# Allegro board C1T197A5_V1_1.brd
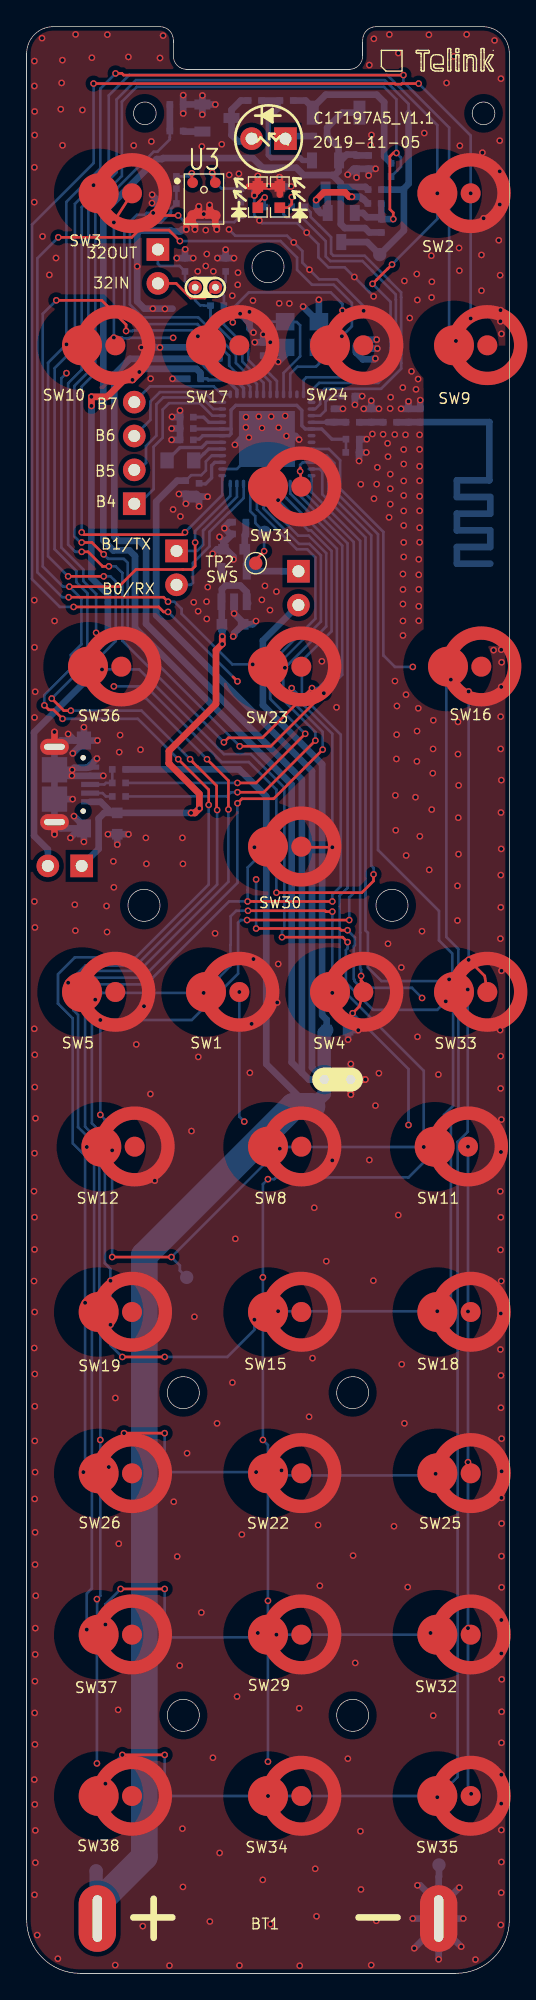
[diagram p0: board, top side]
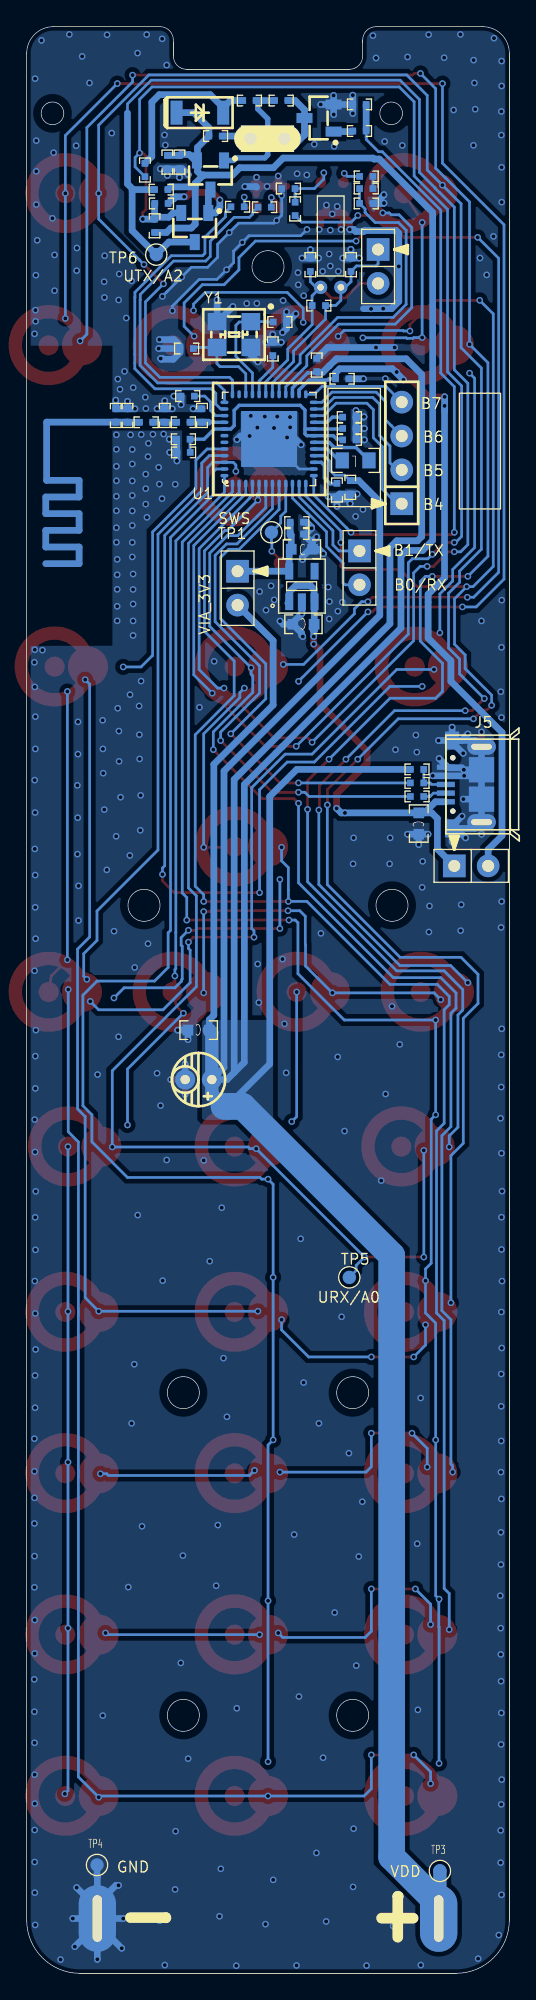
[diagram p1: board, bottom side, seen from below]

Outline 36.2 x 146 mm; copper layers: TOP, BOTTOM. Coordinates in mm from the lower left corner of the outline.
Outline path: circle c8.8,80.1 r1.2 ; circle c8.86,139.5 r0.85 ; circle c11.75,43.55 r1.2 ; circle c11.75,19.35 r1.2 ; circle c18.1,128 r1.2 ; circle c24.45,43.55 r1.2 ; circle c24.45,19.35 r1.2 ; circle c27.4,80.1 r1.2 ; circle c34.26,139.5 r0.85 ; 0,144 0,4 ; 0,144 arc(0.59,145.41) 2,146 10,146 arc(10.71,145.71) 11,145 ; 0,144 0,4 ; 0,4 arc(1.17,1.17) 4,0 ; 4,0 32.2,0 ; 4,0 32.2,0 ; 32.2,0 arc(35.03,1.17) 36.2,4 36.2,144 arc(35.61,145.41) 34.2,146 26.2,146 arc(25.49,145.71) 25.2,145 25.2,144.8 ; 11,145 11,144.8 ; 11,145 11,144.8 ; 11,144.8 11,143.8 arc(11.29,143.09) 12,142.8 ; 12,142.8 24.2,142.8 ; 12,142.8 24.2,142.8 ; 24.2,142.8 arc(24.91,143.09) 25.2,143.8 ; 25.2,144.8 25.2,143.8 ; 25.2,144.8 25.2,143.8

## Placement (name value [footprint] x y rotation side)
BT1  3V_2xAAA  [BAT_2DIP]  18.1 4.11 0 top
C1  NC  [0402]  23.05 116.84 270 bottom
C2  1.2pF  [0402]  25.84 116.84 270 bottom
C3  2.7pF  [0402]  28.64 116.84 270 bottom
C4  220pF  [0402]  24.45 116.33 0 bottom
C5  0.1uF  [0402]  24.45 115.06 180 bottom
C6  2.2uF  [0402]  24.43 114.07 180 bottom
C7  1uF  [0402]  24.12 118.29 0 bottom
C8  1.5pF  [0402]  29.52 116.84 90 bottom
C9  1uF  [0402]  17.74 121.83 270 bottom
C10  1uF  [0402]  14.45 120.62 90 bottom
C11  1uF  [0402]  12.54 119.59 180 bottom
C12  1uF  [0402]  12.93 111.25 90 bottom
C13  NC  [0402]  24.2 121.86 180 bottom
C14  NC  [0402]  17.21 123.85 0 bottom
C15  1uF  [0402]  11.93 111.45 90 bottom
C16  1uF  [0402]  12 115.01 0 bottom
C17  0.1uF  [0402]  12 115.86 0 bottom
C18  1uF  [0402]  12 116.71 0 bottom
C19  NC  [0402]  11.87 128.14 270 bottom
C20  NC  [0402]  14.92 128.14 270 bottom
C21  NC/10uF  [0603C]  15.56 106.81 180 bottom
C22  NC/0.1uF  [0402]  15.94 107.95 180 bottom
C23  NC/10uF  [0603C]  15.44 101.18 0 bottom
C24  10uF  [0603C]  23.3 70.74 0 bottom
C25  NC/10uF  [0603C]  6.79 86.23 270 bottom
C26  10nF  [0402]  10.73 134.77 0 bottom
C27  10pF  [0402]  10.73 132.74 180 bottom
C28  4.7uF  [0402]  16.57 133.86 0 bottom
C31  4.7uF  [0402]  24.74 135.84 270 bottom
C32  0.1uF  [0402]  25.65 135.84 270 bottom
C33  NC/1nF  [0402]  15.94 108.84 180 bottom
CD1  NC  [CD2P0_4P0B]  23.31 67.03 0 bottom
D1  Red_LED  [0603-LED]  17.34 133.22 90 top
D2  Red_LED  [0603-LED]  18.99 133.22 90 top
D3  LED  [LED_TH_2P54MM_2PIN]  18.14 137.6 0 top
D4  1N4148  [SOD80]  23.21 139.55 180 bottom
J1  NC/HEADER 4  [HDR254F-1X4X850]  8.07 117.84 270 bottom
J2  NC/HEADER 2  [HDR254F-1X2X850]  11.24 104.14 90 bottom
J3  HEADER 2  [HDR254F-1X2X850]  9.84 126.75 90 bottom
J4  NC/2PIN  [HDR254F-1X2X850]  20.38 102.62 90 bottom
J5  NC/USB_MiniABF  [MICROUSB_DIP]  4.76 87.87 90 bottom
J42  RF_SOC_5V  [HDR254F-1X2X850]  1.59 83.06 0 bottom
L1  2.7nH  [0402]  27.24 116.33 0 bottom
L3  4.7uH  [0805L]  11.53 113.47 0 bottom
Q1  A1015  [SOT-23]  22.41 134.87 0 bottom
Q2  C1815  [SOT-23]  14.27 139.15 90 bottom
Q3  C1815  [SOT-23]  23.59 130.94 0 bottom
R1  1K  [0402]  18.35 132.46 180 bottom
R2  1K  [0402]  20.38 132.49 180 bottom
R3  NC  [0402]  14.29 125.08 0 bottom
R4  NC/33  [0402]  6.92 88.27 180 bottom
R5  NC/33  [0402]  6.92 89.28 180 bottom
R6  NC/1.5K  [0402]  6.92 90.3 0 bottom
R7  0R  [0402]  16.06 132.33 90 bottom
R8  000R  [0402]  10.73 133.86 180 bottom
R10  1  [0402]  22.03 137.79 0 bottom
R11  NC  [0402]  11.24 140.17 180 bottom
R12  10K  [0402]  26.11 133.78 180 bottom
R13  100  [0402]  11.24 138.18 0 bottom
R14  10K  [0402]  17.11 140.46 0 bottom
R15  22K  [0402]  19.49 140.46 0 bottom
R16  10K  [0402]  26.09 132.74 180 bottom
R17  47K  [0402]  27.33 135.25 270 bottom
R18  NC  [0402]  26.61 131.06 90 bottom
SW1  SW2PIN  [SW_OUT6_IN3]  13.45 73.6 180 top
SW2  SW2PIN  [SW_OUT6_IN3]  30.8 133.5 180 top
SW3  SW2PIN  [SW_OUT6_IN3]  5.4 133.5 180 top
SW4  SW2PIN  [SW_OUT6_IN3]  22.75 73.6 180 top
SW5  SW2PIN  [SW_OUT6_IN3]  4.15 73.6 180 top
SW8  SW2PIN  [SW_OUT6_IN3]  18.1 62 180 top
SW9  SW2PIN  [SW_OUT6_IN3]  32.05 122.1 180 top
SW10  SW2PIN  [SW_OUT6_IN3]  4.15 122.1 180 top
SW11  SW2PIN  [SW_OUT6_IN3]  30.6 62 180 top
SW12  SW2PIN  [SW_OUT6_IN3]  5.6 62 180 top
SW15  SW2PIN  [SW_OUT6_IN3]  18.1 49.6 180 top
SW16  SW2PIN  [SW_OUT6_IN3]  31.6 98 180 top
SW17  SW2PIN  [SW_OUT6_IN3]  13.45 122.1 180 top
SW18  SW2PIN  [SW_OUT6_IN3]  30.8 49.6 180 top
SW19  SW2PIN  [SW_OUT6_IN3]  5.4 49.6 180 top
SW22  SW2PIN  [SW_OUT6_IN3]  18.1 37.5 180 top
SW23  SW2PIN  [SW_OUT6_IN3]  18.1 98 180 top
SW24  SW2PIN  [SW_OUT6_IN3]  22.75 122.1 180 top
SW25  SW2PIN  [SW_OUT6_IN3]  30.8 37.5 180 top
SW26  SW2PIN  [SW_OUT6_IN3]  5.4 37.5 180 top
SW29  SW2PIN  [SW_OUT6_IN3]  18.1 25.4 180 top
SW30  SW2PIN  [SW_OUT6_IN3]  18.1 84.5 180 top
SW31  SW2PIN  [SW_OUT6_IN3]  18.1 111.5 180 top
SW32  SW2PIN  [SW_OUT6_IN3]  30.8 25.4 180 top
SW33  SW2PIN  [SW_OUT6_IN3]  32.05 73.6 180 top
SW34  SW2PIN  [SW_OUT6_IN3]  18.1 13.3 180 top
SW35  SW2PIN  [SW_OUT6_IN3]  30.8 13.3 180 top
SW36  SW2PIN  [SW_OUT6_IN3]  4.6 98 180 top
SW37  SW2PIN  [SW_OUT6_IN3]  5.4 25.4 180 top
SW38  SW2PIN  [SW_OUT6_IN3]  5.4 13.3 180 top
TP1  SWS  [TP100]  17.84 108.08 180 bottom
TP2  SWS  [TP100]  17.18 105.76 0 top
TP3  VDD  [TP100]  5.21 7.68 180 bottom
TP4  GND  [TP100]  30.92 8.13 180 bottom
TP5  URX  [TP100]  12 52.2 180 bottom
TP6  UTX  [TP100]  26.48 128.91 180 bottom
U1  TLSR8278F1KET48  [QFN_7X7_48PIN_0P5_4P20X4P20]  18.02 115.08 90 bottom
U2  CE1132-33M  [SOT-23-5]  15.56 104.01 180 bottom
U3  MWW7037AT2  [GA_BFA423_A83]  13.3 133.07 0 top
Y1  24MHz-12pF-+/-20ppm  [OSCCC250X320X110]  20.65 122.91 270 bottom
Y2  32.768KHz - 9pf - +/-20ppm  [OSC_2X6]  13.4 130.45 270 bottom

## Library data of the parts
BT1 = BATTERY_2xAAA_3V
C1-C4 C8 C19 C20 = C1608_NC
C5-C7 C9-C11 C22 C32 C33 = C1005X5R1C104K
C12 C15-C18 = C1005X5R1C105K
C13 C14 = C1005_NC
C21 C23 C25 = C1608X5R1A106K
C24 = C1608X5R0J106M
C26-C28 = C1608X5R0J475M
C31 = C1608X5R1A226M
CD1 = CD_220uF_16V
D1 D2 = 0603D_Red
D3 = Led_Th_3mm_1: User Part Number: partnum; Tolerance: RichardLC
D4 = Diode_1N4148
J1 = HEADER 4: User Part Number: pn; Tolerance: RichardLC
J2 J3 = HEADER 2: User Part Number: pn; Tolerance: RichardLC
J4 = B2S_2: User Part Number: pn; Tolerance: RichardLC
J5 = USB_MiniABF_2
J42 = B2S_3: User Part Number: pn; Tolerance: RichardLC
L1 = MLK1608_000R
L3 = IND_0
Q1 = PNP_A1015
Q2 Q3 = NPN_C1815
R1 R2 R6-R8 = RS0402K472JT
R3 = RS0603K102JT
R4 R5 = RS0402K330JT
R10 = RS0805K1R0JT
R11 R18 = RS0402_NC
R12 R14 R16 = RS0402K103JT
R13 = RS0402K101JT
R15 = RS0402K223JT
R17 = RS0402K473JT
SW1-SW5 SW8-SW12 SW15-SW19 SW22-SW26 SW29-SW38 = SW2PIN_0
TP1-TP6 = TestPad100
U1 = TLSR8278F1KET48_2
U2 = XC6219_6.3V_SOT-23-5
U3 = MULPS4CX-RM5_0
Y1 = CRYSTAL4/SM_0: Tolerance: RichardLC
Y2 = OSC_2x6_2pin_16Mhz

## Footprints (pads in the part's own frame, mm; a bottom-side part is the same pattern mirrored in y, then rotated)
0402
  rect 0.5x0.5 smd: 1(-0.5,0) 2(0.5,0)
0603-LED
  rect 0.8x0.8 smd: A(-0.8,0) C(0.8,0)
0603C
  rect 0.8x0.8 smd: 1(-0.8,0) 2(0.8,0)
0805L
  rect 1x1.2 smd: 1(-1,0) 2(1,0)
BAT_2DIP
  oval 2.8x5 hole 0.7x3.5: 1(-12.8,0) 2(12.8,0)
CD2P0_4P0B
  round 1.5 hole 0.7: 1(-1,0) 2(1,0)
GA_BFA423_A83
  round 0.8 smd: 1(-0.85,1.23) 2(-0.85,-1.23) 3(0.85,-1.23) 4(0.85,1.23)
HDR254F-1X2X850
  rect 1.7x1.7 hole 0.9: 1(2.54,0)
  round 1.7 hole 0.9: 2(0,0)
HDR254F-1X4X850
  rect 1.7x1.7 hole 0.9: 1(7.62,0)
  round 1.7 hole 0.9: 2(5.08,0) 3(2.54,0) 4(0,0)
LED_TH_2P54MM_2PIN
  rect 1.7x1.7 hole 0.9: A(1.27,0)
  round 1.7 hole 0.9: C(-1.27,0)
MICROUSB_DIP
  round 0.4 hole 0.6 unplated: (-0.7,-0.525) (3.3,-0.525)
  rect 0.4x1.35 smd: 1(0,0) 2(0.65,0) 3(1.3,0) 4(1.95,0) 5(2.6,0)
  oval 1.2x2.15 hole 0.45x1.55: 6(-1.525,-2.675) 7(4.125,-2.675)
  rect 1.9x1.9 smd: 8(0.2,-2.675) 9(2.4,-2.675)
  rect 1.35x1.07 smd: 10(-1.996,-0.468) 11(4.596,-0.468)
OSC_2X6
  round 1 hole 0.5: 1(4,0.76) 2(4,-0.76)
OSCCC250X320X110
  rect 1.3x1.4 smd: 1(-0.965,1.265) 2(-0.965,-1.265) 3(0.965,-1.265) 4(0.965,1.265)
QFN_7X7_48PIN_0P5_4P20X4P20
  oval 0.6x0.26 smd: 1(-3.35,2.75) 2(-3.35,2.25) 3(-3.35,1.75) 4(-3.35,1.25) 5(-3.35,0.75) 6(-3.35,0.25) 7(-3.35,-0.25) 8(-3.35,-0.75) 9(-3.35,-1.25) 10(-3.35,-1.75) 11(-3.35,-2.25) 12(-3.35,-2.75) 25(3.35,-2.75) 26(3.35,-2.25) 27(3.35,-1.75) 28(3.35,-1.25) 29(3.35,-0.75) 30(3.35,-0.25) 31(3.35,0.25) 32(3.35,0.75) 33(3.35,1.25) 34(3.35,1.75) 35(3.35,2.25) 36(3.35,2.75)
  oval 0.26x0.6 smd: 13(-2.75,-3.35) 14(-2.25,-3.35) 15(-1.75,-3.35) 16(-1.25,-3.35) 17(-0.75,-3.35) 18(-0.25,-3.35) 19(0.25,-3.35) 20(0.75,-3.35) 21(1.25,-3.35) 22(1.75,-3.35) 23(2.25,-3.35) 24(2.75,-3.35) 37(2.75,3.35) 38(2.25,3.35) 39(1.75,3.35) 40(1.25,3.35) 41(0.75,3.35) 42(0.25,3.35) 43(-0.25,3.35) 44(-0.75,3.35) 45(-1.25,3.35) 46(-1.75,3.35) 47(-2.25,3.35) 48(-2.75,3.35)
  rect 4.2x4.2 smd: 49(0,0)
SOD80
  rect 0.9x1.8 smd: A(-1.75,0) C(1.75,0)
SOT-23
  rect 0.75x1.2 smd: 1(-1.016,-1.092) 2(1.016,-1.092) 3(0,1.092)
SOT-23-5
  rect 0.6x1.25 smd: 1(-0.95,-1.145) 2(0,-1.145) 3(0.95,-1.145) 4(0.95,1.145) 5(-0.95,1.145)
SW_OUT6_IN3
  round 3 smd: 1(0,0)
  custom 1.5x1.5 smd: 2(-2.5,0)
TP100
  round 1 smd: 1(0,0)

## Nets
1V4: C5.2 C6.2 C16.2 C17.2 U1.19(VDD1V2) U1.20(AVDD1V2#20) U1.41(AVDD1V2#41)
GND: BT1.2(-) C1.1 C2.1 C3.1 C5.1 C6.1 C7.2 C8.2 C9.1 C10.2 C11.2 C12.1 C13.1 C14.1 C15.1 C16.1 C17.1 C18.1 C19.1 C20.1 C21.2 C22.2 C23.2 C24.2 C25.2 C27.2 C28.2 C31.2 C32.2 C33.2 CD1.2 D1.C(CATHODE) D2.C(CATHODE) J5.4(ID) J5.5(GND) J5.6(S1) J5.7(S2) J5.8(S3) J5.9(S4) J5.10(S5) J5.11(S6) Q2.2(E) R11.1 TP4.1(TP) U1.14(DVSS) U1.49(GND) U2.2(VSS) U3.2(GND#2) U3.3(GND#3) Y1.2 Y1.4
TL_32KI_C3: C20.2 J3.2 R3.2 U1.31(P1/URX/SCK/32KIN/C[3]) Y2.2
TL_32KO_C2: C19.2 J3.1 R3.1 U1.30(P0/7816TRX/UTX/SDA/32KO/C[2]) Y2.1
TL_ANT: C1.2 C4.1 U1.40(ANT)
TL_AUDIO_C1: C27.1 R8.1 U1.29(SCK/P1N/P0/AUDIO_IN/C[1])
TL_B0: J2.2 U1.10(P3/URX/ATSEL1/MDEC/B[0])
TL_B1: J2.1 U1.11(P4/UTX/ATSEL2/B[1])
TL_B4: J1.1 U1.22(SDMP0/P4/CMP_D/B[4])
TL_B5: J1.2 U1.23(SDMN0/P5/CMP_DF/B[5])
TL_B6: J1.3 U1.24(SDMP1/DI/SDA/URTS/B[6])
TL_B7: J1.4 U1.25(SDMN1/DO/URX/B[7])
TL_C0: R7.1 U1.28(SDA/P4N/URTS/MDEC/C[0])
TL_COL0: SW1.1 SW2.1 SW3.1 SW4.1 SW5.1 U1.36(P3N/URX/ATSEL0/C[5])
TL_COL1: SW8.1 SW9.1 SW10.1 SW11.1 SW12.1 TP5.1(TP) U1.2(DMIC_DI/P0N/URX/MDEC/A[0])
TL_COL2: SW15.1 SW16.1 SW17.1 SW18.1 SW19.1 U1.12(P5/UCTS/CYC2LNA/B[2])
TL_COL3: SW22.1 SW23.1 SW24.1 SW25.1 SW26.1 U1.6(CK/SCL/URTS/P2/A[4])
TL_COL4: SW29.1 SW30.1 SW31.1 SW32.1 SW37.1 U1.5(DI/SDA/UCTS/P1/A[3])
TL_COL5: SW33.1 SW34.1 SW35.1 SW36.1 SW38.1 U1.45(P1N/I2SSDI/7816TRX/UTX/D[3])
TL_DM: R4.1 U1.7(DM/A[5])
TL_DP: R5.1 U1.8(DP(SWS)/A[6])
TL_IRCONTROL: Q3.2(E) R16.1 R17.2 R18.2 U1.3(DMIC_CLK/7816CLK/I2SCLK/A[1])
TL_IRIN: Q3.3(C) R12.1 TP6.1(TP) U1.4(DO/UTX/P0/A[2])
TL_IROUT: R11.2 R13.1 U1.13(P0N/URTS/CYC2PA/B[3])
TL_LED1: R1.1 U1.37(CYC2LNA/ATSEL1/P4N/C[6])
TL_LED2: R2.1 U1.38(CYC2PA/ATSEL2/P5N/C[7])
TL_ROW0: SW1.2 SW8.2 SW15.2 SW22.2 SW29.2 SW34.2 U1.47(P0/CMP_D/P0N/D[5])
TL_ROW1: SW2.2 SW9.2 SW16.2 SW23.2 SW30.2 SW33.2 U1.44(CN/I2SLR/P3/D[2])
TL_ROW2: SW3.2 SW10.2 SW17.2 SW24.2 SW31.2 SW36.2 U1.46(SWM/I2SSDO/P2N/D[4])
TL_ROW3: SW4.2 SW11.2 SW18.2 SW25.2 SW32.2 SW35.2 U1.48(CN/URX/ATSEL0/D[6])
TL_ROW4: SW5.2 SW12.2 SW19.2 SW26.2 SW37.2 SW38.2 U1.1(CK/SCL/I2SBCK/7816TRX/UTX/D[7])
TL_RST: C7.1 U1.39(RESETB)
TL_SWS: TP1.1(TP) TP2.1(TP) U1.9(SWS/URTS/A[7])
TL_VBUS: C11.1 J42.2 U1.26(VBUS)
TL_VDD: BT1.1(+) C10.1 C15.2 C24.1 C31.1 C32.1 CD1.1 D4.A J4.2 Q1.2(E) R6.2 R10.2 R12.2 R18.1 TP3.1(TP) U1.16(VDD_IO) U1.27(VDD3)
TL_XC1: C13.2 U1.34(XC1) Y1.3
TL_XC2: C14.2 U1.33(XC2) Y1.1
USB_5V: C23.1 C25.1 J5.1(V_BUS) J42.1 U2.1(VIN) U2.3(CE)
N21000893: D2.A(ANODE) R2.2
N21007782: D1.A(ANODE) R1.2
N21081547: C21.1 C22.1 C33.1 J4.1 U2.5(VOUT)
N21108187: D3.A(ANODE) R10.1
N21108227: D4.C R15.2 R17.1
N21108333: Q2.1(B) R13.2
N21108349: D3.C(CATHODE) Q2.3(C) R14.1
N21108369: Q1.3(C) Q3.1(B) R16.2
N21108379: Q1.1(B) R14.2 R15.1
N21115397: C3.2 C8.1 L1.2
N21115407: C2.2 C4.2 L1.1
N21116055: C12.2 U1.15(VDD1V)
N21116211: L3.2 U1.17(VDCDC_SW)
N21116214: L3.1 U1.18(VDCDC)
N21116508: C18.2 U1.21(VDD_F)
N21117063: C9.2 U1.32(VMID)
N21119406: J5.3(D+) R5.2 R6.1
N21119472: J5.2(D-) R4.2
N21128727: C28.1 R7.2 U3.4(VDD)
N21128765: C26.1 R8.2
N21128767: C26.2 U3.1(OUTPUT)

Pads without a net: U1 35 42 43; U2 4

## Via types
v1: diameter 0.5, hole 0.3, TOP to BOTTOM, 610 vias

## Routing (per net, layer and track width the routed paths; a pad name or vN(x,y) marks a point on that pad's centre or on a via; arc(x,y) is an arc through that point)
1V4: length 19.1
  BOTTOM w0.2: 15.33,115.83 15.32,115.83 15.3,115.83 ; C6.2 23.95,114.09 C5.2
  BOTTOM w0.25: C5.2 22.89,115.06 22.12,115.83 U1.41 21.36,115.82 20.89,115.82 20.64,116.08 20.64,117.22 20.26,117.6 15.68,117.6 15.33,117.25 15.33,115.47 15.19,115.33 U1.19 13.21,115.33 12.95,115.07 12.56,115.07 C16.2 ; C17.2 12.54,115.83 U1.20 15.3,115.83
GND: length 191.7
  TOP w0.5: D1.C 16.68,134.02 ; D1.C v1(17.34,134.8) ; D1.C 17.34,133.69 17.08,133.44 v1(17.08,133.34) ; D1.C v1(18.17,134.02) D2.C ; v1(18.96,134.71) 18.99,134.68 D2.C ; v1(12.62,130.79) 12.62,131.08 12.45,131.26 U3.2 ; U3.2 11.97,131.36 v1(11.97,130.79) ; U3.2 12.91,132.31 v1(12.91,132.52) ; U3.2 13.16,131.84 13.27,131.95 v1(13.28,131.95) 13.39,131.95 13.5,131.84 U3.3 ; D2.C 18.99,133.4 ; J5.6 v1(2.09,85.42) ; 30.9,4.88 BT1.2 30.9,3.71 ; U3.3 14.15,131.15 14.26,131.04 v1(14.26,130.79) ; U3.3 13.72,132.27 v1(13.72,132.62) ; v1(24.31,65.91) CD1.2 v1(25.4,67.03) ; J5.7 v1(2.09,93.1)
  BOTTOM w0.2: v1(10.37,124.83) 10.92,124.83 10.94,124.85 ; C28.2 17.07,131.85 v1(17.45,131.47) 17.66,131.26 20.3,131.26 v1(21,130.56) 21.88,129.68 21.88,128.7 22.63,127.95 23.85,127.95 v1(24.57,127.22) 25.68,126.12 25.68,126.11 v1(26.02,125.77) ; v1(25.27,124.69) 25.28,124.7 25.28,125.03 23.27,127.04 21.94,127.04 v1(21.21,127.77) 20.68,128.3 20.68,129.17 v1(20.03,129.82) 19.53,130.32 15.64,130.32 v1(15.18,130.79) ; U1.14 15.77,112.83 U1.49 ; 14.27,121.12 C10.2
  BOTTOM w0.5: C13.1 24.7,122.08 25.15,122.53 v1(26.25,122.53) ; C13.1 24.7,121.56 25.21,121.05 26.09,121.05 v1(26.15,121.11) 25.98,121.11 ; C13.1 v1(26.3,121.86) ; v1(14.46,107.73) 14.76,107.43 14.76,107.27 ; v1(5.75,89.82) J5.4 v1(3.39,89.82) 2.54,89.82 J5.9 ; v1(5.27,91.11) 4.76,90.6 J5.5 4.6,90.47 4.55,90.42 3.56,90.42 v1(3.41,90.27) J5.9 ; 3.99,85.87 J5.10 ; 3.99,85.87 2.56,85.87 J5.6 J5.8 ; 3.99,85.87 v1(3.28,85.16) ; J5.10 4.29,86.05 v1(3.55,86.79) ; J5.10 v1(4.29,84.86) ; v1(3.11,92.95) 3.6,92.46 ; 3.6,92.46 2.56,92.46 J5.7 J5.9 ; 3.6,92.46 4.29,92.46 ; v1(11.89,129.3) 11.87,129.28 C19.1 ; C6.1 v1(24.93,113.43) ; C6.1 24.95,114.09 C5.1 v1(25.51,115.06) ; C6.1 v1(25.47,114.07) ; C25.2 v1(7.64,85.43) ; C25.2 v1(6.79,84.66) ; C25.2 v1(6.1,85.43) ; v1(17.01,123.06) 16.71,123.36 C14.1 ; C9.1 v1(17.74,122.92) ; C9.1 v1(17.11,122.33) ; C9.1 v1(18.27,122.33) ; 30.9,5.21 30.9,4.88 ; 30.9,5.21 30.9,7.23 30.92,7.25 TP4.1 ; 30.9,5.21 29.51,6.6 v1(29.31,6.6) ; 30.9,4.88 BT1.2 ; 30.9,4.88 v1(32.45,6.43) ; v1(9.4,132.77) 9.43,132.74 10.04,132.74 ; 18.02,115.44 16.92,115.44 v1(16.67,115.19) 16.67,115.61 16.36,115.92 ; 18.02,115.44 v1(19.39,116.81) ; 18.02,115.44 18.02,116.34 17.56,116.8 ; 18.02,115.44 18.02,115.18 ; 18.02,115.44 19.37,115.44 19.52,115.29 ; 10.04,132.74 9.41,133.37 v1(9.41,133.4) ; 10.04,132.74 C27.2 ; C3.1 C8.2 v1(29.52,117.99) ; C3.1 v1(28.64,117.9) ; C3.1 v1(28.08,117.34) ; v1(13.95,106.47) 13.95,106.48 14.27,106.81 C21.2 ; CD1.2 v1(24.31,68.2) ; C17.1 C16.1 v1(10.87,115.01) ; C17.1 11.5,115.86 C18.1 ; C17.1 v1(10.87,115.86) ; 18.02,115.18 U1.49 16.06,115.08 v1(15.62,114.64) ; 18.02,115.18 16.51,116.69 ; C10.2 13.63,121.94 v1(10,121.94) v1(8.6,121.94) ; C14.1 v1(16.71,124.61) ; C14.1 16.63,123.85 v1(16.01,124.47) ; v1(13.17,139.41) 13.18,139.42 Q2.2 ; C12.1 v1(12.93,110.03) ; C12.1 v1(13.57,110.75) ; C12.1 12.74,110.56 11.96,110.56 11.96,110.24 v1(11.94,110.22) ; C12.1 12.73,110.95 C15.1 v1(11.42,110.95) ; v1(21.92,125.52) Y1.2 21.87,123.88 v1(20.73,125.01) ; v1(19.84,134.01) 19.01,134.01 18.95,133.95 ; C31.2 24.52,135.34 v1(24.08,134.9) ; C31.2 C32.2 ; C31.2 v1(24.74,134.69) ; C20.1 v1(14.92,129.27) ; C20.1 v1(15.55,128.64) ; C20.1 v1(14.3,128.64) ; v1(17.2,101.42) 16.96,101.18 C23.2 ; 30.9,3.69 v1(30.9,1.05) ; 30.9,3.69 v1(32.59,2) ; 30.9,3.69 30.9,3.71 ; 4.29,92.46 4.29,92.33 v1(3.46,91.5) ; 4.29,92.46 v1(4.29,93.46) ; 4.29,92.46 v1(5.31,92.46) ; Q2.2 v1(14.15,140.16) ; Q2.2 11.74,140.16 R11.1 ; Q2.2 v1(13.18,140.84) ; v1(18.86,120.86) 19.39,121.39 Y1.4 ; BT1.2 v1(28.96,4.11) ; BT1.2 v1(32.74,4.11) ; BT1.2 30.9,3.71 ; C21.2 14.95,106.81 15.51,106.25 v1(15.51,106.04) ; C21.2 14.76,107.27 ; C33.2 15.21,108.84 14.83,108.46 v1(14.83,108.38) 15.26,107.95 C22.2 14.76,107.27 ; C23.2 15.57,100.51 15.57,100.34 v1(15.49,100.26) ; C23.2 16.24,101.3 v1(15.56,101.99) U2.2 ; 30.9,3.71 v1(29.07,1.88) ; R11.1 v1(11.74,140.86) ; R11.1 v1(11.74,139.49) ; C19.1 v1(11.26,128.64) ; C19.1 v1(12.49,128.64) ; v1(11.97,130.79) 11.68,130.79 11.53,130.64 10.92,130.64 10.85,130.71 8.49,130.71 8.29,130.51 v1(8.29,128.02) 8.29,125.39 8.83,124.85 v1(9.46,124.85) 10.94,124.85 ; v1(19.48,115.3) 20.16,115.3 v1(20.43,115.03) ; C2.1 v1(26.42,117.34) ; C2.1 v1(25.84,117.94) ; C2.1 v1(25.28,117.34) ; J5.9 J5.8 ; C18.1 10.93,116.71 v1(10.9,116.74) ; C18.1 v1(11.5,117.21) ; J5.8 v1(3.45,88.07) ; C32.2 v1(25.65,134.84) ; C32.2 v1(26.17,135.34) ; v1(25.16,118.29) C7.2 v1(24.62,117.64) ; v1(24.1,70.03) C24.2 v1(24.87,70.74) ; C11.2 v1(10.94,119.59) ; C1.1 v1(23.72,117.34)
  vias: v1(0.55,58.66) v1(0.55,51.92) v1(0.58,143.42) v1(0.58,141.55) v1(0.6,139.64) v1(0.6,137.87) v1(0.58,135.45) v1(0.57,132.84) v1(0.57,102.99) v1(0.59,99.45) v1(0.64,96.12) v1(0.59,94.19) v1(0.58,80.39) v1(0.62,78.44) v1(0.57,70.84) v1(0.61,68.89) v1(0.61,66.47) v1(0.59,61.51) v1(0.59,56.71) v1(0.59,54.29) v1(0.6,49.6) v1(0.57,46.9) v1(0.61,44.95) v1(0.61,42.53) v1(0.61,39.93) v1(0.63,37.59) v1(0.6,35.58) v1(0.63,33.08) v1(0.63,30.66) v1(0.65,25.89) v1(0.64,23.92) v1(0.62,21.91) v1(0.6,19.53) v1(0.62,17.17) v1(0.57,14.53) v1(0.61,12.67) v1(0.65,10.72) v1(0.65,8.3) v1(0.59,5.89) v1(0.66,64.13) v1(0.68,28.32) v1(0.79,2.87) v1(1.15,145.14) v1(1.19,130.27) v1(1.7,127.38) v1(2.09,101.43) v1(2.2,128.65) v1(2.34,1.1) v1(2.62,141.78) v1(2.56,139.81) v1(2.68,143.49) v1(2.69,137.1) v1(3.61,80.15) v1(3.67,145.42) v1(3.65,78.2) v1(4.18,139.75) v1(4.89,143.67) v1(6.05,145.4) v1(5.99,80.05) v1(6.03,78.1) v1(6.5,83.4) v1(6.54,81.45) v1(6.65,43.15) v1(6.64,0.62) v1(6.94,91.59) v1(6.91,32.22) v1(6.86,19.76) v1(7.01,92.87) v1(7.63,143.73) v1(8.03,137.09) v1(8.22,69.67) v1(8.54,91.77) v1(8.71,3.54) v1(8.8,72.53) v1(8.94,85.16) v1(8.98,83.21) v1(9.35,137.39) v1(9.3,119.6) v1(9.28,65.95) v1(9.61,59.45) v1(10,143.65) v1(10.23,145.33) v1(10.71,0.58) v1(10.98,109.79) v1(11.03,35.37) v1(11.29,31.26) v1(11.53,109.27) v1(11.48,23.08) v1(11.68,85.16) v1(11.72,83.21) v1(11.68,10.85) v1(11.72,6.48) v1(12.03,39.01) v1(12.36,63.17) v1(12.53,102.83) v1(12.58,49.24) v1(12.83,127.65) v1(12.86,102.16) v1(12.87,68.73) v1(13.14,137.02) v1(13.1,27.06) v1(13.43,130.74) v1(13.43,128.05) v1(13.51,128.95) v1(13.49,102.88) v1(13.51,101.58) v1(13.58,103.97) v1(13.74,3.89) v1(14,127.65) v1(13.97,16.17) v1(14.13,78) v1(14.28,41.25) v1(14.47,9.03) v1(14.63,137.18) v1(15.19,134.88) v1(15.42,125.82) v1(15.43,44.31) v1(15.65,55.09) v1(15.85,127.55) v1(15.83,126.64) v1(15.78,20.76) v1(15.92,134.97) v1(15.96,0.59) v1(16.14,32.91) v1(16.45,116.72) v1(16.44,115.95) v1(16.74,67.54) v1(16.87,71.21) v1(16.97,125.46) v1(17.01,76.07) v1(17.41,116.76) v1(17.64,103.01) v1(17.65,115.9) v1(17.71,7.01) v1(17.87,104.06) v1(18.25,102.24) v1(18.34,116.76) v1(18.29,3.69) v1(18.73,103.63) v1(18.79,72.81) v1(18.94,125.25) v1(18.9,115.93) v1(18.87,75.7) v1(19.7,125.24) v1(20.44,19.88) v1(20.48,0.57) v1(21.18,41.74) v1(21.44,46.14) v1(21.57,57.42) v1(21.64,7.84) v1(21.74,4.28) v1(21.86,33.62) v1(21.99,29.07) v1(22.14,98.4) v1(22.47,53.41) v1(22.92,60.97) v1(23.24,94.95) v1(24.09,16.1) v1(24.48,31.33) v1(24.64,23.28) v1(25.03,10.66) v1(25.06,111.68) v1(25.07,6.29) v1(25.7,143.12) v1(25.7,61) v1(25.8,137.12) v1(25.84,0.62) v1(25.86,137.88) v1(25.93,115.45) v1(26.04,145.09) v1(26,51.95) v1(26.05,110.6) v1(26.25,111.69) v1(26.16,65.08) v1(26.22,3.94) v1(26.3,112.95) v1(26.42,67.51) v1(26.73,115.43) v1(27.07,114.75) v1(27.1,113.75) v1(27.1,77.22) v1(27.2,145.41) v1(27.18,109.2) v1(27.3,118.21) v1(27.26,117.36) v1(27.27,112.44) v1(27.27,111.35) v1(27.27,110.19) v1(27.61,115.41) v1(27.62,96.92) v1(27.65,88.35) v1(27.55,33.53) v1(27.73,91.08) v1(27.68,85.73) v1(27.77,95.05) v1(27.75,92.9) v1(27.88,144.02) v1(27.87,56.87) v1(28.1,75.44) v1(28.13,45.68) v1(28.21,118.93) v1(28.22,104.95) v1(28.22,103.79) v1(28.22,102.7) v1(28.22,101.43) v1(28.22,100.34) v1(28.33,126.93) v1(28.28,114.29) v1(28.28,113.2) v1(28.28,111.93) v1(28.28,110.84) v1(28.28,109.68) v1(28.28,108.59) v1(28.28,107.32) v1(28.28,106.23) v1(28.33,41.25) v1(28.41,115.39) v1(28.45,95.9) v1(28.46,83.84) v1(28.58,28.97) v1(28.73,124.15) v1(28.86,120.15) v1(29.2,118.8) v1(29.16,88.21) v1(29.26,127.45) v1(29.3,125.5) v1(29.28,93.17) v1(29.27,90.9) v1(29.31,70.24) v1(29.36,119.57) v1(29.41,106.05) v1(29.41,104.89) v1(29.41,103.8) v1(29.41,102.53) v1(29.41,101.44) v1(29.37,94.88) v1(29.47,115.39) v1(29.47,114.3) v1(29.47,113.03) v1(29.47,111.94) v1(29.47,110.78) v1(29.47,109.69) v1(29.47,108.42) v1(29.47,107.33) v1(29.49,85.28) v1(29.65,78.16) v1(29.82,138.02) v1(30.17,145.39) v1(30.19,82.76) v1(30.35,128.82) v1(30.39,126.87) v1(30.37,125.69) v1(30.38,87.28) v1(30.5,93.98) v1(30.48,91.83) v1(30.46,90.01) v1(30.49,19.33) v1(30.88,67.41) v1(31.49,141.78) v1(32.04,143.77) v1(32.31,81.56) v1(32.31,78.96) v1(32.43,129.4) v1(32.45,127.7) v1(32.35,93.86) v1(32.35,91.44) v1(32.4,89.1) v1(32.37,86.67) v1(32.39,83.94) v1(32.49,137.07) v1(33,145.42) v1(33.66,1.03) v1(34.11,128.88) v1(34.11,126.2) v1(34.18,136.55) v1(34.27,131.63) v1(35.02,99.24) v1(35.09,144.97) v1(35.41,129.98) v1(35.48,137.45) v1(35.48,135.15) v1(35.48,132.66) v1(35.51,127.36) v1(35.54,124.74) v1(35.53,123.9) v1(35.53,77.6) v1(35.51,70.74) v1(35.52,58.65) v1(35.54,54.26) v1(35.53,46.79) v1(35.57,142.1) v1(35.61,122.96) v1(35.59,99.27) v1(35.62,98.33) v1(35.59,96.48) v1(35.55,94.25) v1(35.55,91.83) v1(35.6,89.49) v1(35.57,87.06) v1(35.59,84.33) v1(35.56,82.37) v1(35.56,79.95) v1(35.61,75.19) v1(35.55,68.79) v1(35.55,66.37) v1(35.6,64.03) v1(35.57,61.6) v1(35.56,56.7) v1(35.59,51.92) v1(35.56,49.49) v1(35.57,44.84) v1(35.57,42.42) v1(35.62,40.1) v1(35.62,37.65) v1(35.61,35.66) v1(35.62,33.74) v1(35.61,31.29) v1(35.62,28.95) v1(35.6,26.5) v1(35.6,23.99) v1(35.63,22.05) v1(35.62,19.62) v1(35.61,17.29) v1(35.6,14.9) v1(35.59,12.73) v1(35.6,10.75) v1(35.6,8.35) v1(35.59,6.05) v1(35.56,3.63)
TL_32KI_C3: length 16.5
  TOP w0.2: Y2.2 13.36,125.65 12.31,125.65 11.21,126.75 J3.2
  BOTTOM w0.2: U1.31 18.27,119.36 17.58,120.04 16.62,121 16.62,121.82 14.79,123.65 R3.2 14.79,125.09 14.79,125.81 Y2.2 14.5,126.45 14.92,126.87 C20.2
TL_32KO_C2: length 15.6
  BOTTOM w0.2: J3.1 9.84,128.21 10,128.05 11.46,128.05 C19.2 11.87,126.87 12.3,126.45 Y2.1 12.64,125.47 13.02,125.09 13.3,125.09 13.31,125.08 R3.1 13.79,124.06 16.04,121.81 16.04,121.81 16.18,121.67 16.18,120.88 17.77,119.29 U1.30
TL_ANT: length 2.6
  BOTTOM w0.25: 22.55,116.34 22.53,116.33 U1.40
  BOTTOM w0.5: 22.55,116.34 C1.2 23.95,116.34 C4.1
TL_AUDIO_C1: length 24.3
  BOTTOM w0.2: U1.29 17.27,119.2 15.69,120.78 15.69,121.38 12.88,124.19 8.72,124.19 7.74,125.17 7.74,130.73 8.32,131.31 10.06,131.31 10.81,132.06 10.81,132.07 10.82,132.08 10.82,132.33 C27.1 R8.1
TL_B0: length 10.3
  BOTTOM w0.2: U1.10 16.27,110.65 15.15,109.53 15.12,109.53 13.71,108.12 13.71,107.02 12.47,105.78 12.47,104.29 12.32,104.14 J2.2
TL_B1: length 7.8
  BOTTOM w0.2: J2.1 12.78,106.68 13.23,107.13 13.23,108.2 13.31,108.28 13.31,108.28 14.96,109.93 14.96,109.93 15.77,110.74 U1.11
TL_B4: length 13.5
  BOTTOM w0.2: 8.43,110.22 8.19,109.98 ; 8.43,110.22 J1.1 ; 8.43,110.22 9.52,111.31 9.52,114.49 10.2,115.17 10.2,117.28 10.68,117.76 12.99,117.76 13.92,116.83 U1.22
TL_B5: length 11.7
  BOTTOM w0.2: 8.19,112.52 8.43,112.76 ; 8.43,112.76 8.95,113.28 8.95,114.55 9.73,115.33 9.73,117.68 10.24,118.19 13.13,118.19 14,117.33 U1.23 ; 8.43,112.76 J1.2
TL_B6: length 9.1
  BOTTOM w0.2: J1.3 9.28,116.51 9.28,117.88 9.99,118.59 13.3,118.59 14.06,117.83 U1.24
TL_B7: length 7.9
  BOTTOM w0.2: U1.25 14.63,118.43 14.04,119.02 9.25,119.02 J1.4
TL_C0: length 28.6
  TOP w0.2: v1(9.49,132.03) 9.97,132.03 10.16,131.84 v1(11.36,131.84)
  BOTTOM w0.2: v1(11.36,131.84) 11.86,131.34 15.57,131.34 R7.1 ; v1(9.49,132.03) 9.01,132.03 8.87,131.89 8.27,131.89 7.32,130.94 7.32,124.92 8.55,123.69 12.81,123.69 15.19,121.31 15.19,120.57 16.77,119 U1.28
TL_COL0: length 171.4
  TOP w0.2: v1(22.92,79.63) 22.45,79.63 22.38,79.69 v1(16.6,79.69) ; v1(3.31,94.7) 2.79,94.7 v1(1.88,95.61) ; v1(5.14,73.03) 4.57,73.6 SW5.1 ; v1(25.94,126.71) 26.28,127.05 26.28,127.05 27.05,127.82 27.06,127.82 v1(27.4,128.16) ; v1(14.29,87.25) 14.29,87.36 14.24,87.4 14.24,89.07 12.8,90.51 12.79,90.51 12.47,90.83 12.47,90.85 v1(12.26,91.06)
  BOTTOM w0.2: v1(5.14,73.03) 5.65,73.53 v1(13.27,73.53) 15.28,75.55 15.28,77.13 15.3,77.15 15.3,79.28 15.71,79.69 v1(16.6,79.69) ; U1.36 20.77,119.49 20.98,119.7 26.21,119.7 27.29,120.78 27.29,125.36 v1(25.94,126.71) ; v1(27.4,128.16) 27.74,128.5 27.74,128.51 30.8,131.57 v1(30.8,133.5) 30.8,138.61 27.03,142.39 7.7,142.39 6.16,140.84 6.16,135.25 v1(5.02,134.11) 3.62,132.72 3.62,121.92 2.09,120.4 2.09,106.81 3.73,105.17 3.73,104.33 4.56,103.5 4.56,99.4 3.83,98.67 3.83,98.66 3.73,98.56 3.73,97.46 v1(1.88,95.61) ; v1(12.26,91.06) 8.61,94.7 v1(3.31,94.7) ; v1(22.92,79.63) v1(22.92,73.53) ; 14.29,87.38 v1(14.29,87.25) 14.29,81.66 8.21,75.58 4.4,75.58 v1(3.11,74.3)
TL_COL1: length 236.2
  TOP w0.2: v1(28.26,142.37) 7.27,142.37 7.14,142.49 v1(6.67,142.49) ; v1(13.53,91.06) 15.13,89.45 v1(15.13,87.29) ; v1(2.98,122.17) 3.06,122.1 SW10.1 ; v1(10.86,53.72) v1(6.41,53.72) ; v1(3.11,104.78) v1(5.78,104.78)
  BOTTOM w0.2: v1(6.67,142.49) 5.52,141.35 5.52,135.38 4.8,134.66 4.79,134.66 2.98,132.86 v1(2.98,122.17) 1.61,120.8 1.61,106.28 v1(3.11,104.78) ; v1(4.51,61.98) 4.51,62.81 3.85,63.46 3.85,71.88 3.49,72.24 3.49,73.79 4.89,75.18 8.45,75.18 15.13,81.87 v1(15.13,87.29) ; v1(32.19,122.43) 31.69,122.94 31.69,138.43 28.26,141.86 v1(28.26,142.37) ; TP5.1 11.49,52.71 11.49,53.09 v1(10.86,53.72) v1(18.99,61.85) 19.46,61.85 19.59,61.98 v1(29.78,61.98) 29.78,67.69 23.47,74 23.47,80.81 24.07,81.41 24.07,107.25 20.27,111.04 U1.2 ; v1(6.41,53.72) v1(6.41,61.72) ; v1(5.78,104.78) 6.29,104.78 6.68,104.38 6.68,99.92 5.02,98.26 5.02,96.14 5.52,95.63 8.95,95.63 v1(13.53,91.06)
TL_COL2: length 202.1
  TOP w0.2: v1(12.64,107.31) 12.64,105.54 12.38,105.28 11.72,105.28 11.72,105.29 8.2,105.29 6.91,104 v1(3.2,104) ; SW15.1 17.66,49.6 v1(17.08,49.02) ; 6.29,48.9 6.16,48.77 ; 6.16,48.77 6.03,48.77 5.4,49.27 SW19.1 ; 6.16,48.77 v1(6.29,48.64) ; v1(11.37,91.06) 13.65,88.77 v1(13.65,87.63) ; v1(10.35,46.23) v1(7.17,46.23) ; v1(2.22,125.48) 5.63,125.48 7.46,123.65 v1(7.46,123.17) ; v1(1.33,95.1) 1.67,94.76 2.02,94.76 v1(2.69,94.09)
  BOTTOM w0.2: v1(12.84,122.78) 12.41,123.21 7.97,123.21 7.93,123.17 v1(7.46,123.17) ; v1(6.29,48.64) 6.29,47.12 v1(7.17,46.23) ; v1(11.37,91.06) 8.34,94.09 v1(2.69,94.09) ; v1(4.38,50.29) 4.38,61.33 3.45,62.25 3.45,71.63 2.35,72.73 2.35,74.93 3.62,76.2 8.19,76.2 13.65,81.66 v1(13.65,87.63) ; v1(1.33,95.1) 1.33,95.87 3.31,97.86 3.31,98.89 4.11,99.68 4.11,103.09 v1(3.2,104) 2.72,104 1.21,105.52 1.21,124.46 v1(2.22,125.48) ; v1(18.86,49.66) v1(30.8,49.66) 31.81,50.67 31.81,64.26 32.38,64.83 32.38,76.82 31.48,77.72 31.48,96.69 v1(31.81,97.03) ; v1(17.08,49.02) 17.08,48.26 15.05,46.23 v1(10.35,46.23) ; v1(12.64,107.31) 12.64,108.17 15.27,110.8 U1.12
TL_COL3: length 192.3
  TOP w0.2: SW23.1 18.18,97.92 v1(19.37,97.92) ; v1(7.3,40.51) v1(10.35,40.51) ; v1(15.81,87.76) 16.15,88.09 18.52,88.09 v1(22.2,91.78) ; v1(11.49,129.92) 10.67,130.74 8.42,130.74 7.88,130.2 v1(2.37,130.2) ; v1(3.15,103.21) 10.27,103.21 v1(10.6,102.87)
  BOTTOM w0.2: v1(16.95,98.17) 15.43,98.17 14.46,99.14 14.44,99.14 11.62,101.97 11.62,102.33 11.08,102.87 v1(10.6,102.87) ; v1(4.25,37.59) 4.25,38.07 4.38,38.2 4.38,49.02 5.06,49.7 5.06,62.82 4.38,63.5 4.38,72.01 4,72.39 4,73.53 5.14,74.68 8.7,74.68 15.81,81.79 v1(15.81,87.76) ; U1.6 18.27,109.93 18.92,109.28 20.37,107.82 21.16,107.82 22.47,106.51 22.47,101.02 v1(19.37,97.92) 19.37,97.44 19.24,97.31 19.24,96.07 22.2,93.11 v1(22.2,91.78) 22.29,91.69 ; v1(19.11,37.72) 19.49,37.34 30.07,37.34 30.19,37.47 v1(30.67,37.47) ; v1(23.64,122.78) 24.39,123.53 24.39,125.28 23.02,126.64 21.4,126.64 20.28,127.76 20.28,128.68 19.04,129.92 v1(11.49,129.92) ; v1(2.37,130.2) 0.8,128.63 0.8,105.08 2.67,103.21 v1(3.15,103.21) ; v1(17.21,37.59) 10.75,37.59 10.35,37.99 v1(10.35,40.51) ; v1(6.16,37.97) 6.16,39.37 v1(7.3,40.51)
TL_COL4: length 138.9
  TOP w0.2: v1(7.05,28.83) v1(10.35,28.83) ; v1(22.92,80.39) 17.05,80.39 17.05,80.39 v1(16.57,80.39) ; 18.05,84.45 SW30.1 ; v1(17.34,25.53) 17.46,25.4 SW29.1
  BOTTOM w0.2: v1(18.73,25.4) 30.16,25.4 v1(30.29,25.53) ; v1(5.91,26.16) 5.91,27.69 v1(7.05,28.83) ; v1(17.08,84.45) 17.08,83.44 16.57,82.93 16.57,81.25 16.57,81.25 v1(16.57,80.39) 15.18,80.39 8.95,74.17 5.4,74.17 4.51,73.28 4.51,72.64 4.89,72.26 4.89,63.75 5.46,63.18 5.46,49.53 4.89,48.96 4.89,28.87 4.51,28.49 v1(4.51,25.78) ; v1(10.35,28.83) 10.35,25.65 10.81,25.19 17,25.19 v1(17.34,25.53) ; v1(22.92,80.39) 22.92,80.9 23.56,81.53 23.56,92.89 20.64,95.82 20.64,98.42 22.87,100.65 22.87,106.68 21.32,108.22 21.13,108.22 v1(18.86,110.49) 18.86,110.97 18.77,111.06 U1.5
TL_COL5: length 181.6
  TOP w0.2: v1(33.08,73.79) 32.96,73.66 SW33.1 ; v1(7.17,16.38) v1(10.35,16.38) ; v1(19.15,77.71) 23.7,77.71 v1(24.07,77.34)
  BOTTOM w0.2: v1(5.91,14.22) 5.91,15.11 v1(7.17,16.38) ; v1(19.15,77.71) 19.15,78.19 19.32,78.36 19.32,88.93 17.45,90.8 16.81,91.44 14.79,91.44 8.45,97.79 v1(5.65,97.79) ; v1(31.69,74.55) 31.92,74.78 31.92,76.47 30.92,77.47 30.92,79.68 26.35,84.25 26.35,107.93 23.07,111.21 23.07,113.26 22.51,113.83 U1.45 ; v1(31.43,72.9) 30.8,72.26 25.97,72.26 23.94,74.3 23.94,76.74 24.07,76.87 v1(24.07,77.34) ; 30.7,13.3 v1(30.8,13.21) ; 30.7,13.3 v1(18.1,13.3) 10.89,13.3 10.35,13.84 v1(10.35,16.38) ; 30.7,13.3 30.89,13.3 32.32,14.73 32.32,62.36 33.08,63.12 v1(33.08,73.79)
TL_DM: length 40.1
  TOP w0.2: v1(15.81,88.58) 17.78,88.58 v1(21.65,92.46)
  BOTTOM w0.2: v1(15.81,88.58) 15.33,88.58 15.02,88.27 R4.1 ; v1(21.65,92.46) 21.65,93.09 18.73,96.01 18.73,98.04 18.82,98.13 18.82,98.14 19.14,98.47 19.16,98.47 22.07,101.38 22.07,106.35 21.21,107.21 20.42,107.21 17.77,109.86 U1.7
TL_DP: length 38.5
  TOP w0.2: v1(15.81,89.28) 17.21,89.28 v1(20.89,92.96)
  BOTTOM w0.2: U1.8 17.27,109.8 20.26,106.81 21.04,106.81 21.65,106.2 21.65,101.6 18.27,98.21 18.27,95.59 v1(20.89,92.96) ; R5.1 v1(15.81,89.28)
TL_IRCONTROL: length 119.3
  TOP w0.2: v1(27.73,136.53) 27.5,136.53 27.24,136.27 27.24,132.3 27.5,132.05 v1(27.5,131.57) ; v1(4.13,107.31) 4.89,107.31 v1(5.78,106.43) ; v1(22.29,96.01) 18.31,92.03 v1(15.98,92.03)
  BOTTOM w0.2: v1(5.78,106.43) 6.12,106.09 7.28,106.09 7.58,105.79 7.58,100.44 15.98,92.03 v1(15.98,92.03) ; v1(4.13,107.31) 4.03,107.31 3.58,107.77 3.58,119.06 4.63,120.11 4.63,132.3 7.14,134.8 7.14,140.37 8.25,141.48 26.8,141.48 27.73,140.55 v1(27.73,136.53) 28.07,136.19 28.07,135.49 R17.2 ; v1(22.29,96.01) 23.67,97.39 23.67,107.08 19.77,110.98 U1.3
  BOTTOM w0.5: v1(27.5,131.57) 27.49,131.56 R18.2 ; R18.2 26.46,131.71 25.54,131.71 25.21,132.03 Q3.2 ; R18.2 26.61,132.72 R16.1
TL_IRIN: length 122.4
  TOP w0.2: v1(14.79,92.33) 15.13,92.67 17.67,92.67 v1(21.4,96.39) ; v1(4.13,106.61) 4.6,106.61 5.67,105.55 5.67,105.54 5.69,105.52 v1(6.17,105.52)
  BOTTOM w0.2: U1.4 19.27,110.86 19.49,110.63 19.49,110.62 23.27,106.84 23.27,97.78 21.88,96.39 v1(21.4,96.39) ; v1(6.17,105.52) 6.68,105.52 7.18,105.03 7.18,99.95 v1(14.79,92.33) ; 28.64,139.52 28.64,140.21 26.86,141.99 8.19,141.99 6.74,140.54 6.74,135.07 5.57,133.9 5.57,133.88 5.24,133.56 5.23,133.56 4.13,132.46 4.13,120.27 3.11,119.25 3.11,107.15 3.65,106.61 v1(4.13,106.61)
  BOTTOM w0.5: 28.64,139.52 28.64,134.21 28.21,133.78 ; Q3.3 25.54,129.84 TP6.1 28.29,130.72 28.29,133.7 28.21,133.78 ; 28.21,133.78 R12.1
TL_IROUT: length 48.3
  TOP w0.2: v1(11.87,108.08) 11.7,107.9 4.3,107.9 v1(4.13,108.08)
  BOTTOM w0.2: U1.13 14.67,110.87 12.21,108.41 12.21,108.41 v1(11.87,108.08) ; R13.1 10.74,137.7 10.73,137.69 10.73,137.54 9.81,136.62 9.52,136.62 5.14,132.24 5.14,120.02 4.13,119 v1(4.13,108.08)
  BOTTOM w0.5: R11.2 R13.1
TL_LED1: length 25.6
  BOTTOM w0.2: R1.1 19.26,132.05 19.26,131.93 19.49,131.7 20.64,131.7 22.43,129.91 22.43,128.76 22.77,128.42 25.19,128.42 25.91,127.69 25.91,127.68 27.68,125.91 27.68,125.54 27.69,125.53 27.69,120.6 26.37,119.28 21.93,119.28 21.37,118.71 U1.37
TL_LED2: length 25
  BOTTOM w0.2: R2.1 21.29,132.08 21.29,131.74 21.92,131.11 21.93,131.11 22.83,130.21 22.83,129 23.01,128.82 25.35,128.82 27.17,127 27.17,126.99 28.08,126.08 28.08,125.7 28.09,125.69 28.09,121.43 28.09,120.35 26.58,118.84 22.35,118.84 22.02,118.5 22.02,117.7 21.64,117.33 U1.38
TL_ROW0: length 126.4
  TOP w0.2: 20.6,49.69 SW15.2
  BOTTOM w0.2: U1.47 21.98,112.83 22.17,112.64 22.17,110.93 25.41,107.69 25.41,78.22 25.59,78.04 25.59,75.44 26.61,74.42 30.92,74.42 31.98,73.36 31.98,65.07 31.3,64.39 31.3,62.36 28.64,59.69 18.7,59.69 18.57,59.56 v1(18.1,59.56) 17.72,59.18 v1(17.72,52.2) v1(17.72,40.01) 18.1,39.62 v1(18.1,27.94) v1(18.1,15.88) ; v1(15.95,73.6) 15.95,64.25 v1(16.32,63.88)
TL_ROW1: length 181.8
  TOP w0.2: 29.08,97.98 v1(28.96,97.98) ; v1(22.92,84.45) 20.64,84.45 SW30.2 ; v1(29.4,141.73) 28.15,141.73 28.1,141.69 27.65,141.69 27.61,141.73 v1(5.02,141.73) ; v1(17.21,78.36) 23.46,78.36 23.59,78.23 v1(24.07,78.23) ; SW33.2 34.35,74.8 v1(33.15,76.01) ; v1(3.52,102.48) 9.9,102.48 10.27,102.11 v1(10.6,102.11) ; v1(15.81,96.9) 15.47,97.24
  BOTTOM w0.2: v1(29.65,73.15) 28.89,73.91 25.08,73.91 24.57,74.42 24.57,74.53 24.53,74.58 24.53,77.03 24.62,77.12 24.62,77.68 v1(24.07,78.23) ; v1(33.3,124.12) v1(33.3,133.5) 33.3,137.83 v1(29.4,141.73) ; v1(33.15,96.14) v1(33.15,76.01) ; v1(17.21,78.36) v1(17.21,82.04) ; v1(19.88,96.39) 20.21,96.06 20.21,95.67 22.92,92.96 v1(22.92,84.45) ; v1(15.81,96.9) v1(10.6,102.11) ; v1(28.96,97.98) 27.62,97.98 26.79,98.81 26.75,98.85 26.75,108.11 23.51,111.35 23.51,113.48 22.66,114.33 U1.44 ; v1(3.52,102.48) 2.49,102.48 0.4,104.56 0.4,131.15 5.02,135.76 v1(5.02,141.73)
TL_ROW2: length 115.3
  TOP w0.2: v1(6.54,131.32) 6.41,131.19 SW3.2 ; SW31.2 20.51,112.9 v1(20.51,112.65) ; v1(26.01,82.42) 26.01,81.93 25.14,81.05 v1(18.73,81.05) ; 15.46,124.11 v1(15.46,123.83)
  BOTTOM w0.2: v1(23.68,124.71) 23.68,125.19 22.81,126.07 16.66,126.07 15.46,124.87 v1(15.46,123.83) ; v1(10.98,122.66) 7.72,122.66 7.68,122.62 7.23,122.62 7.17,122.68 v1(6.54,122.68) v1(6.54,131.32) ; v1(18.73,81.05) 18.73,88.77 16.66,90.85 14.63,90.85 8.95,96.52 v1(6.54,96.52) ; v1(26.01,82.42) 26.01,82.9 25.84,83.07 25.84,107.85 22.63,111.06 22.63,112.94 22.25,113.33 U1.46 20.71,113.33 20.51,113.13 v1(20.51,112.65) ; v1(2.98,120.02) 2.6,119.63 2.6,106.93 4.25,105.29 4.25,104.42 5.21,103.46 v1(5.21,100.54)
TL_ROW3: length 102.6
  TOP w0.2: SW25.2 33.3,38.14 v1(33.1,38.34) ; v1(24.45,72.01) 24.95,72.52 SW4.2 25.08,73.95 25.08,74.45 ; 25.08,74.45 v1(25.08,74.8) ; 25.08,74.45 25.25,74.28 ; SW32.2 33.3,25.69 v1(33.1,25.89)
  BOTTOM w0.2: v1(33.34,13.46) 33.1,13.7 v1(33.1,25.89) v1(33.1,38.34) v1(33.1,49.64) v1(33.1,62) ; v1(24.45,72.01) 28.64,67.82 v1(28.64,63.63) ; v1(25.08,74.8) 25.08,75.28 25.02,75.35 25.02,78.05 25.01,78.05 25.01,107.43 21.37,111.08 U1.48
TL_ROW4: length 115.1
  TOP w0.2: v1(6.29,51.94) 6.15,51.8 ; v1(16.53,78.99) v1(24.19,78.99)
  BOTTOM w0.2: v1(24.19,78.99) 24.19,80.69 24.53,81.03 24.53,107.35 20.77,111.11 U1.1 ; v1(16.53,78.99) 16.05,78.99 15.85,78.8 15.85,74.97 12.38,71.5 v1(5.52,71.5) v1(5.52,64.39) 5.86,64.05 5.86,53.26 6.29,52.83 v1(6.29,51.94) 6.29,49.53 5.52,48.77 v1(5.52,40.01) 5.52,28.32 v1(5.27,28.07) 5.27,27.85 5.29,27.84 5.29,26 5.27,25.98 v1(5.27,15.75)
TL_RST: length 3.2
  BOTTOM w0.2: U1.39 22.02,116.83 22.41,117.22 22.41,117.86 22.84,118.29 C7.1
TL_SWS: length 6.7
  TOP w0.2: TP2.1 17.18,106.03 v1(17.81,106.66)
  BOTTOM w0.2: U1.9 16.77,109.66 17.14,109.28 17.14,108.78 TP1.1 17.84,107.35 17.81,107.32 v1(17.81,106.66)
TL_VBUS: length 53.3
  TOP w0.5: v1(8.45,120.1) 8.45,120.02 v1(7.94,119.51) 7.31,119.51 6.04,118.24 v1(4.85,118.24) 4.86,118.23 v1(4.86,117.56)
  BOTTOM w0.25: C11.1 13.54,119.59 13.63,119.5 15.03,119.5 15.77,118.76 U1.26
  BOTTOM w0.5: 4.86,117.17 4.85,117.17 v1(4.85,118.24) ; 4.86,117.17 v1(4.86,117.56) ; 4.86,117.17 4.86,104.66 6.09,103.43 6.09,102.83 6.09,100.15 4.38,98.44 4.38,96.9 0.55,93.07 0.55,85.32 1.59,84.28 J42.2 ; C11.1 13.04,120.03 12.73,120.34 8.77,120.34 v1(7.94,119.51)
TL_VDD: length 386.9
  BOTTOM w0.2: 13.94,113.83 13.88,113.83 13.44,113.39 13.44,112.71 13.09,112.36 12.34,112.36 C15.2
  BOTTOM w0.25: C10.1 14.53,120.04 15.12,120.04 16.27,118.89 U1.27 ; U1.16 13.94,113.83
  BOTTOM w0.5: 20.64,67.56 21.17,67.03 CD1.1 21.4,67.95 21.4,90.17 9.71,101.85 9.71,110.38 11.29,111.95 C15.2 ; 20.64,67.56 20.64,89.53 8.95,101.22 8.95,106.93 8.45,107.44 6.89,107.44 6.57,107.76 6.57,119.92 7.74,121.09 12.97,121.09 13.5,120.56 13.51,120.56 13.99,120.08 14.41,120.08 C10.1 ; 20.64,67.56 19.88,68.33 19.88,89.15 17.52,91.51 17.04,91.99 8.13,100.9 8.13,106.3 7.7,106.72 6.5,106.72 5.75,107.47 5.75,132.07 9.75,136.07 10.15,136.07 10.22,136.14 16.97,136.14 17.69,135.42 20.22,135.42 20.77,134.87 22.91,134.87 ; J4.2 17.72,99.95 17.72,95.12 22.16,90.68 22.16,71.86 22.5,71.52 C24.1 ; 22.91,134.87 22.95,134.83 22.98,134.83 23.56,134.25 23.56,133.99 ; 22.91,134.87 23.11,134.87 23.39,135.15 23.39,135.78 ; D4.A 23.66,139.55 22.53,138.42 R10.2 23.39,136.94 23.39,135.78 ; 23.56,133.99 23.56,131.19 23.85,130.89 25.38,130.89 25.71,130.56 R18.1 ; 23.56,133.99 25.41,133.99 R12.2 ; 23.39,135.78 23.43,135.82 23.43,135.97 23.57,135.97 24.01,136.41 24.67,136.41 C31.1 C32.1 ; 21.14,65.02 17.97,68.2 17.97,88.27 15.94,90.3 R6.2
  BOTTOM w1: 21.4,65.02 22.31,65.94 CD1.1 22.31,70.55 C24.1 ; TP3.1 5.21,4.2 BT1.1
  BOTTOM w2: BT1.1 5.3,5.21 8.83,8.74 8.83,53.85 20,65.02 21.4,65.02
TL_XC1: length 7.1
  BOTTOM w0.2: C13.2 23.61,121.94 Y1.3 21.93,121.93 21.93,120.73 21.7,120.5 20.3,120.5 19.77,119.96 U1.34
TL_XC2: length 8.6
  BOTTOM w0.2: U1.33 19.27,120.03 20.51,121.27 20.51,123.6 20.26,123.85 19.41,123.85 Y1.1 18.21,123.88 18.19,123.85 C14.2
USB_5V: length 37.6
  TOP w0.5: v1(14.67,100.26) v1(14.67,99.69) 14.2,99.23 14.2,95.21 10.67,91.68 10.67,90.77 10.67,90.77 10.67,90.74 12.95,88.46 v1(12.95,87.38) 12.95,87.36 12.62,87.03 v1(12.33,87.03)
  BOTTOM w0.5: 14.63,100.71 14.8,100.88 ; 14.63,100.71 14.63,102.84 U2.3 14.64,102.9 14.64,103.81 14.91,104.08 16.02,104.08 16.51,103.6 U2.1 16.61,102.76 ; 14.63,100.71 14.67,100.67 ; 6.38,87.03 5.54,87.87 J5.1 ; 6.38,87.03 5.82,87.03 5.4,86.61 5.4,84.33 J42.1 ; 6.38,87.03 C25.1 12.61,87.03 v1(12.95,87.38) ; v1(14.67,100.26) 14.67,100.67 ; 14.67,100.67 14.67,101.15 C23.1
N21000893: length 2.3
  TOP w0.2: D2.A 19.61,132.42 19.88,132.69 v1(19.88,133.22)
  BOTTOM w0.2: R2.2 v1(19.88,133.22)
N21007782: length 1.8
  TOP w0.2: D1.A 17.34,132.79 17.73,133.19 v1(17.85,133.19)
  BOTTOM w0.2: R1.2 v1(17.85,133.19)
N21081547: length 7.7
  BOTTOM w0.5: C33.1 C22.1 16.36,107.87 16.36,106.81 16.51,106.66 U2.5 19.15,105.16 19.16,105.16 J4.1
N21108187: length 2.2
  BOTTOM w0.5: D3.A 19.61,137.79 R10.1
N21108227: length 12.9
  BOTTOM w0.5: R17.1 26.81,136.27 26.81,140.34 26.25,140.9 22.43,140.9 21.46,139.93 21.46,139.92 ; D4.C 21.46,139.92 ; 21.46,139.92 20.92,140.46 R15.2
N21108333: length 1.5
  BOTTOM w0.5: R13.2 11.78,138.13 Q2.1
N21108349: length 5.2
  BOTTOM w0.5: R14.1 16.06,140.46 15.36,139.76 Q2.3 15.36,137.87 15.38,137.87 15.86,137.39 16.66,137.39 D3.C
N21108369: length 7.9
  TOP w0.5: v1(21.71,133) 22.29,133.58 23.87,133.58 24.21,133.24 v1(24.39,133.24)
  BOTTOM w0.5: R16.2 25.25,133.08 25.17,133.08 25.01,133.24 v1(24.39,133.24) ; v1(21.71,133) 21.71,132.44 21.84,132.31 21.84,132.23 22.04,132.03 Q3.1 22.58,133.62 Q1.3
N21108379: length 9.3
  BOTTOM w0.4: Q1.1 20.7,135.97 20.5,136.16 18.34,136.16 18.12,136.38 18.12,139.09 18.87,139.83 18.87,140.33 R15.1
  BOTTOM w0.5: R15.1 R14.2
N21115397: length 32.5
  BOTTOM w0.5: L1.2 28.64,116.33 C3.2 C8.1 34.7,116.34 34.7,111.97 32.27,111.97 32.27,110.72 34.77,110.72 34.77,109.47 32.27,109.47 32.27,108.22 34.77,108.22 34.77,106.97 32.27,106.97 32.27,105.72 34.77,105.72
N21115407: length 1.8
  BOTTOM w0.5: L1.1 26.74,116.34 C2.2 25.84,116.33 C4.2
N21116055: length 3
  BOTTOM w0.25: C12.2 12.97,111.71 13.42,111.71 13.87,112.16 13.87,113.08 14.11,113.33 U1.15
N21116211: length 2.5
  BOTTOM w0.25: L3.2 12.78,113.47 13.29,113.98 13.31,113.98 13.65,114.33 U1.17
N21116214: length 4.7
  BOTTOM w0.25: L3.1 11.5,114.44 13.12,114.44 13.52,114.83 U1.18
N21116508: length 2.3
  BOTTOM w0.25: C18.2 13.27,116.71 13.66,116.33 U1.21
N21117063: length 3.3
  BOTTOM w0.2: C9.2 17.74,120.45 18.26,119.92 18.77,119.42 U1.32
N21119406: length 2.7
  BOTTOM w0.2: R6.1 R5.2 5.94,89.28 5.83,89.17 J5.3
N21119472: length 1.8
  BOTTOM w0.2: J5.2 5.69,88.52 5.94,88.27 R4.2
N21128727: length 4.8
  TOP w0.2: U3.4 14.15,134.48 14.05,134.58 14.05,134.91 v1(13.91,135.04)
  BOTTOM w0.2: R7.2 16.06,133.37 16.07,133.38 C28.1 14.62,133.86 13.91,134.57 v1(13.91,135.04)
N21128765: length 0.9
  BOTTOM w0.2: C26.1 R8.2
N21128767: length 2
  TOP w0.2: v1(12.38,135) 12.38,134.37 U3.1
  BOTTOM w0.2: v1(12.38,135) 12.15,134.77 C26.2

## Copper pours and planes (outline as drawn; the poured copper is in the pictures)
GND on TOP: 4,0.3 1.38,1.38 0.3,4 0.3,144 0.8,145.2 2,145.7 10,145.7 10.49,145.49 10.7,145 10.7,143.8 11.08,142.88 12,142.5 24.2,142.5 25.12,142.88 25.5,143.8 25.5,145 25.71,145.49 26.2,145.7 34.2,145.7 35.4,145.2 35.9,144 35.9,4 34.82,1.38 32.2,0.3 ; 2 cut-outs
GND on BOTTOM: 4,0.3 1.38,1.38 0.3,4 0.3,144 0.8,145.2 2,145.7 10,145.7 10.49,145.49 10.7,145 10.7,143.8 11.08,142.88 12,142.5 24.2,142.5 25.12,142.88 25.5,143.8 25.5,145 25.71,145.49 26.2,145.7 34.2,145.7 35.4,145.2 35.9,144 35.9,4 34.82,1.38 32.2,0.3 ; 27 cut-outs
TL_VDD on BOTTOM: 17.72,71.5 17.72,64.01 22.92,64.01 23.05,64.14 23.05,71.37 22.92,71.5

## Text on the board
Ref Des/Silkscreen Bottom: B6 | B5 | B4 | B7 | B0/RX | B1/TX | VDD | URX/A0 | SWS | UTX/A2 | GND | VIA_3V3
User.Comments: Factory | Lot | Note | ZHL2010 | EP7945.41 | TLSR8278F1KET48 | C2=1.2pF L1=2.7nH C3=2.7nH | Date | 2020-04-03 | Designer | Hongwei | AMJ-151029 | AMJ-160130 | +
Ref Des/Silkscreen Top: 32OUT | 32IN | B6 | B5 | B4 | B7 | B1/TX | B0/RX | SWS | 2019-11-05 | C1T197A5_V1.1
COMPVAL_TYPE_BOTTOM: Reference report | the antenna length | Need to shorten | FIGURE | SIZE | 0.3 | 0.5 | 0.7 | 0.9 | 0.6 | 1.55x0.45 | 3.5x0.7 | DRILL CHART: TOP to BOTTOM | ALL UNITS ARE IN MILLIMETERS | PLATED | NON-PLATED | QTY | 610 | 2 | 14
BODY_CENTER: +
